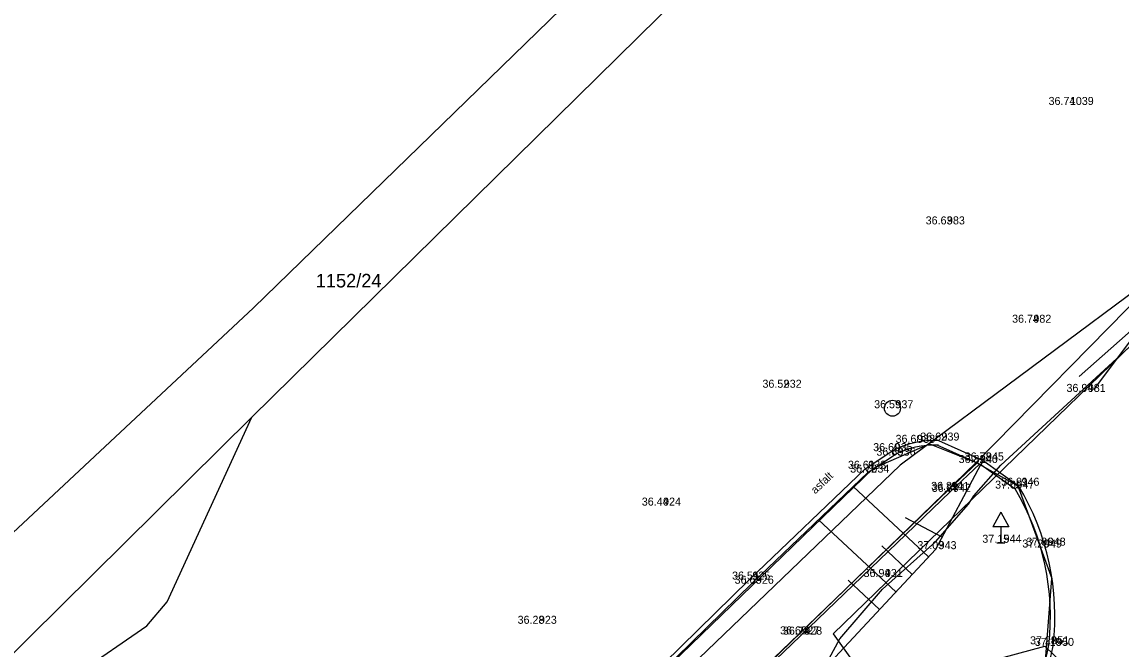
# Model space of a CAD drawing. Extents: x -609709 to -609357, y -1051535 to -1051131.
# Drawn here: x -609619.19 to -609584.85, y -1051247.66 to -1051228.08 of the extents above; entities that cross this region are included whole.
import ezdxf

# ---------------------------------------------------------------- set-up
doc = ezdxf.new("R2010")
doc.units = 0
for name, color, linetype in [('Vrstva 1', 7, 'Continuous'), ('Vrstva 10', 7, 'Continuous'), ('Vrstva 15', 7, 'Continuous'), ('Vrstva 17', 7, 'Continuous'), ('Vrstva 18', 7, 'Continuous'), ('Vrstva 2', 7, 'Continuous'), ('Vrstva 3', 7, 'Continuous'), ('Vrstva 4', 7, 'Continuous'), ('Vrstva 5', 7, 'Continuous'), ('Vrstva 6', 7, 'Continuous'), ('Vrstva 8', 7, 'Continuous')]:
    doc.layers.add(name, color=color, linetype=linetype)

msp = doc.modelspace()

# ---------------------------------------------------------------- linework, layer by layer
at = {"layer": 'Vrstva 1'}
for p, q in [((-609586.54, -1051230.67), (-609586.54, -1051230.67)), ((-609590.38, -1051234.4), (-609590.38, -1051234.4)), ((-609587.68, -1051237.47), (-609587.68, -1051237.47)), ((-609595.48, -1051239.5), (-609595.48, -1051239.5)), ((-609585.98, -1051239.63), (-609585.98, -1051239.63)), ((-609591.99, -1051240.14), (-609591.99, -1051240.14)), ((-609591.31, -1051241.22), (-609591.31, -1051241.22)), ((-609590.55, -1051241.15), (-609590.55, -1051241.15)), ((-609592.01, -1051241.48), (-609592.01, -1051241.48)), ((-609591.92, -1051241.62), (-609591.92, -1051241.62)), ((-609589.35, -1051241.85), (-609589.35, -1051241.85)), ((-609589.16, -1051241.77), (-609589.16, -1051241.77)), ((-609592.84, -1051242.03), (-609592.84, -1051242.03)), ((-609592.74, -1051242.15), (-609592.74, -1051242.15)), ((-609588.05, -1051242.56), (-609588.05, -1051242.56)), ((-609590.24, -1051242.69), (-609590.24, -1051242.69)), ((-609590.19, -1051242.75), (-609590.19, -1051242.75)), ((-609588.21, -1051242.65), (-609588.21, -1051242.65)), ((-609599.25, -1051243.18), (-609599.25, -1051243.18)), ((-609590.64, -1051244.54), (-609590.64, -1051244.54)), ((-609588.61, -1051244.34), (-609588.61, -1051244.34)), ((-609587.35, -1051244.49), (-609587.35, -1051244.49)), ((-609587.23, -1051244.43), (-609587.23, -1051244.43)), ((-609596.46, -1051245.49), (-609596.46, -1051245.49)), ((-609596.35, -1051245.62), (-609596.35, -1051245.62)), ((-609592.32, -1051245.41), (-609592.32, -1051245.41)), ((-609603.13, -1051246.87), (-609603.13, -1051246.87)), ((-609594.93, -1051247.2), (-609594.93, -1051247.2)), ((-609594.84, -1051247.21), (-609594.84, -1051247.21)), ((-609587.12, -1051247.51), (-609587.12, -1051247.51)), ((-609586.97, -1051247.56), (-609586.97, -1051247.56))]:
    msp.add_line(p, q, dxfattribs=at)
at = {"layer": 'Vrstva 10'}
for p, q in [((-609612.01, -1051240.42), (-609562.22, -1051191.46)), ((-609611.96, -1051237), (-609573.91, -1051200.06)), ((-609589.38, -1051241.83), (-609583.95, -1051236.31)), ((-609621.52, -1051245.94), (-609611.96, -1051237)), ((-609626.15, -1051254.4), (-609612.01, -1051240.42)), ((-609614.65, -1051246.18), (-609612.01, -1051240.42)), ((-609592.58, -1051242.01), (-609590.83, -1051241.25)), ((-609590.83, -1051241.25), (-609589.38, -1051241.83)), ((-609622.18, -1051273.63), (-609589.38, -1051241.83)), ((-609589.38, -1051241.83), (-609588.07, -1051242.56)), ((-609623.53, -1051271.88), (-609592.58, -1051242.01)), ((-609588.07, -1051242.56), (-609587.01, -1051245.46)), ((-609587.25, -1051248.49), (-609587.01, -1051245.46)), ((-609615.29, -1051246.93), (-609614.65, -1051246.18)), ((-609626.15, -1051254.4), (-609615.29, -1051246.93))]:
    msp.add_line(p, q, dxfattribs=at)
at = {"layer": 'Vrstva 15'}
for points in [[(-609537.51, -1051208.58), (-609541.98, -1051211.54), (-609559.34, -1051222.57), (-609563.62, -1051224.83), (-609573.15, -1051229.82), (-609581.51, -1051234.92), (-609583.83, -1051237.49), (-609593.84, -1051247.18), (-609592.54, -1051249), (-609587.23, -1051247.57), (-609586.1, -1051248.66), (-609581.84, -1051254.04), (-609580.215, -1051257.976)], [(-609618.56, -1051272.15), (-609610.34, -1051264.5), (-609607, -1051260.39), (-609602.74, -1051257.16), (-609596.84, -1051252.04), (-609595.4, -1051250.72), (-609595.03, -1051249.91), (-609593.64, -1051247.34), (-609592.3, -1051245.79), (-609590.65, -1051244.31), (-609589.61, -1051243.13), (-609589.45, -1051242.87), (-609588.61, -1051241.92), (-609583.43, -1051237.16), (-609581.27, -1051235.22), (-609579.94, -1051234.39), (-609575.07, -1051232.15), (-609567.92, -1051226.6)]]:
    msp.add_lwpolyline(points, dxfattribs=at)
at = {"layer": 'Vrstva 17'}
msp.add_lwpolyline([(-609531.786, -1051180.515), (-609532.61, -1051181.07), (-609528.54, -1051185.58), (-609545.95, -1051201.69), (-609546.72, -1051202.27), (-609551.04, -1051206.15), (-609565.42, -1051219.63), (-609579.77, -1051233.3), (-609583.56, -1051235.84), (-609591.75, -1051241.92), (-609609.05, -1051258.52), (-609618.01, -1051267.11), (-609626.05, -1051275.26), (-609630.23, -1051279.58), (-609635.78, -1051285.7), (-609642.85, -1051291.4), (-609672.95, -1051307.23)], dxfattribs=at)
at = {"layer": 'Vrstva 18'}
for points in [[(-609583.91, -1051237.16), (-609586.16, -1051239.145)], [(-609583.91, -1051237.16), (-609585.706, -1051239.563)]]:
    msp.add_lwpolyline(points, dxfattribs=at)
at = {"layer": 'Vrstva 4'}
msp.add_line((-609592.752, -1051242.14), (-609591.939, -1051241.601), dxfattribs=at)
for points in [[(-609590.55, -1051241.15), (-609589.16, -1051241.77), (-609588.05, -1051242.56)], [(-609592.84, -1051242.03), (-609592.01, -1051241.48)], [(-609592.01, -1051241.48), (-609591.939, -1051241.601)], [(-609590.607, -1051241.278), (-609589.23, -1051241.892), (-609588.155, -1051242.657)], [(-609601.06, -1051253.08), (-609594.93, -1051247.2), (-609590.24, -1051242.69), (-609589.342, -1051241.842)], [(-609601.005, -1051253.138), (-609594.875, -1051247.258), (-609590.185, -1051242.748), (-609589.263, -1051241.878)], [(-609589.16, -1051241.77), (-609589.23, -1051241.892)], [(-609602.18, -1051251.07), (-609600.74, -1051249.68), (-609596.46, -1051245.49), (-609592.84, -1051242.03)], [(-609602.083, -1051251.171), (-609600.642, -1051249.78), (-609596.363, -1051245.591), (-609592.752, -1051242.14)], [(-609592.84, -1051242.03), (-609592.752, -1051242.14)], [(-609588.05, -1051242.56), (-609588.155, -1051242.657)], [(-609590.24, -1051242.69), (-609590.185, -1051242.748)]]:
    msp.add_lwpolyline(points, dxfattribs=at)
for centre, radius, start, end in [((-609590.669, -1051244.018), 2.87, 87.6224, 117.8504), ((-609590.669, -1051244.018), 2.73, 87.6224, 117.7065), ((-609594.8, -1051246.635), 7.884, 353.2595, 31.1177), ((-609594.8, -1051246.635), 7.744, 353.2929, 30.9037), ((-609592.954, -1051246.458), 5.945, 311.2028, 349.5269), ((-609592.954, -1051246.458), 6.085, 311.1529, 349.5703)]:
    msp.add_arc(centre, radius, start, end, dxfattribs=at)
at = {"layer": 'Vrstva 5'}
for p, q in [((-609588.61, -1051243.39), (-609588.86, -1051243.84)), ((-609588.61, -1051243.39), (-609588.36, -1051243.84)), ((-609588.36, -1051243.84), (-609588.86, -1051243.84)), ((-609588.61, -1051243.84), (-609588.61, -1051244.34)), ((-609588.735, -1051244.34), (-609588.485, -1051244.34))]:
    msp.add_line(p, q, dxfattribs=at)
msp.add_circle((-609591.99, -1051240.14), 0.25, dxfattribs=at)
at = {"layer": 'Vrstva 6'}
msp.add_lwpolyline([(-609610.31, -1051288.53), (-609610.4, -1051286.73), (-609612.71, -1051282.35), (-609615.84, -1051278.39), (-609617.55, -1051275.92), (-609615.49, -1051274.55), (-609612.49, -1051270.95), (-609610.45, -1051268.68), (-609607.94, -1051265.3), (-609606.28, -1051264.06), (-609602.59, -1051259.95), (-609593.93, -1051248.07), (-609590.64, -1051244.54), (-609589.23, -1051241.892)], dxfattribs=at)
at = {"layer": 'Vrstva 8'}
for p, q in [((-609590.862, -1051244.779), (-609593.217, -1051242.584)), ((-609591.885, -1051245.876), (-609594.303, -1051243.622)), ((-609590.441, -1051244.166), (-609591.579, -1051243.56)), ((-609591.374, -1051245.327), (-609592.328, -1051244.438)), ((-609592.396, -1051246.425), (-609593.376, -1051245.511))]:
    msp.add_line(p, q, dxfattribs=at)

# ---------------------------------------------------------------- texts
at = {"layer": 'Vrstva 10'}
msp.add_text('1152/24', height=0.425, dxfattribs=at).set_placement((-609610.01, -1051236.369))
at = {"layer": 'Vrstva 2'}
for s, p in [(' 1039', (-609586.54, -1051230.67)), (' 983', (-609590.38, -1051234.4)), (' 982', (-609587.68, -1051237.47)), (' 932', (-609595.48, -1051239.5)), (' 981', (-609585.98, -1051239.63)), (' 937', (-609591.99, -1051240.14)), (' 939', (-609590.55, -1051241.15)), (' 935', (-609592.01, -1051241.48)), (' 938', (-609591.31, -1051241.22)), (' 936', (-609591.92, -1051241.62)), (' 945', (-609589.16, -1051241.77)), (' 933', (-609592.84, -1051242.03)), (' 934', (-609592.74, -1051242.15)), (' 940', (-609589.35, -1051241.85)), (' 941', (-609590.24, -1051242.69)), (' 942', (-609590.19, -1051242.75)), (' 947', (-609588.21, -1051242.65)), (' 946', (-609588.05, -1051242.56)), (' 924', (-609599.25, -1051243.18)), (' 943', (-609590.64, -1051244.54)), (' 944', (-609588.61, -1051244.34)), (' 949', (-609587.35, -1051244.49)), (' 948', (-609587.23, -1051244.43)), (' 925', (-609596.46, -1051245.49)), (' 931', (-609592.32, -1051245.41)), (' 926', (-609596.35, -1051245.62)), (' 923', (-609603.13, -1051246.87)), (' 927', (-609594.93, -1051247.2)), (' 928', (-609594.84, -1051247.21)), (' 951', (-609587.12, -1051247.51)), (' 950', (-609586.97, -1051247.56))]:
    msp.add_text(s, height=0.25, dxfattribs=at).set_placement(p)
at = {"layer": 'Vrstva 3'}
for s, p in [('36.74', (-609587.113, -1051230.67)), ('36.63', (-609590.953, -1051234.4)), ('36.74', (-609588.253, -1051237.47)), ('36.52', (-609596.053, -1051239.5)), ('36.94', (-609586.553, -1051239.63)), ('36.59', (-609592.563, -1051240.14)), ('36.62', (-609591.123, -1051241.15)), ('36.60', (-609592.593, -1051241.48)), ('36.60', (-609591.893, -1051241.22)), ('36.65', (-609592.493, -1051241.62)), ('36.78', (-609589.733, -1051241.77)), ('36.61', (-609593.382, -1051242.03)), ('36.72', (-609593.313, -1051242.15)), ('36.82', (-609589.923, -1051241.85)), ('36.81', (-609590.782, -1051242.69)), ('36.87', (-609590.763, -1051242.75)), ('37.05', (-609588.783, -1051242.65)), ('36.91', (-609588.592, -1051242.56)), ('36.44', (-609599.823, -1051243.18)), ('37.03', (-609591.213, -1051244.54)), ('37.15', (-609589.183, -1051244.34)), ('37.20', (-609587.933, -1051244.49)), ('37.06', (-609587.809, -1051244.43)), ('36.51', (-609597.002, -1051245.49)), ('36.94', (-609592.893, -1051245.41)), ('36.63', (-609596.923, -1051245.62)), ('36.28', (-609603.703, -1051246.87)), ('36.69', (-609595.503, -1051247.2)), ('36.74', (-609595.413, -1051247.21)), ('37.28', (-609587.693, -1051247.51)), ('37.18', (-609587.543, -1051247.56))]:
    msp.add_text(s, height=0.25, dxfattribs=at).set_placement(p)
at = {"layer": 'Vrstva 4'}
msp.add_text('asfalt', height=0.25, rotation=43.7054, dxfattribs=at).set_placement((-609594.402, -1051242.832))

doc.saveas('drawing.dxf')
